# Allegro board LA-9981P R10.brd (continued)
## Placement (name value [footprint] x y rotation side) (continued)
PJP102  -  [JUMP_43X118]  140.05 13.39 270 bottom
PJP103  -  [JUMP_43X118]  117.31 13.51 270 bottom
PJP200  -  [JUMP_43X118]  149.32 27.85 90 top
PJP201  -  [JUMP_43X118]  144.81 27.59 90 bottom
PJP203  -  [JUMP_43X39]  155.03 29.36 270 bottom
PJP300  -  [JUMP_43X118]  143.67 140.45 270 top
PJP400  -  [JUMP_43X79]  108.3 20.35 90 bottom
PJP401  -  [JUMP_43X79]  112.11 31.27 90 bottom
PJP600  -  [JUMP_43X79]  213.98 90.82 0 bottom
PJP601  -  [JUMP_43X79]  215.29 96.76 270 top
PJP1100  -  [JUMP_43X118]  182.78 162.32 270 bottom
PJP1101  -  [JUMP_43X118]  188.12 162.32 270 bottom
PJP1200  -  [JUMP_43X118]  192.27 181.37 0 bottom
PJP1300  -  [JUMP_43X79]  195.74 76.19 270 top
PJP1301  -  [JUMP_43X79]  194.66 58.76 270 bottom
PJPDC  -  [ACES_50299-00501-003_5P]  136.9 178.4 270 bottom
PL1  -  [CHT_C8BBPH853025_2P]  140.43 174 270 bottom
PL2  -  [CHT_C8BBPH853025_2P]  132.93 182.51 180 bottom
PL3  -  [CHENG_SMB3025500YA_2P]  155.86 180.26 90 bottom
PL4  -  [CHT_C8BBPH853025_2P]  132.87 166.13 180 bottom
PL100  -  [VISHAY_IHLP-2525CZ-01_2P]  135.35 25.41 0 bottom
PL101  -  [VISHAY_IHLP-2525CZ-01_2P]  120.17 25.57 180 bottom
PL102  -  [CYNTE_PCMB053T-1R0MS_2P]  127.73 31.78 270 bottom
PL200  -  [TAI-T_VMPI0703AR-1R0M-Z01_2P]  145.4 15.12 0 bottom
PL201  -  [L_1812-1806]  165.32 20.69 270 bottom
PL301  -  [CYNTE_PCMB063T-1R0MS_2P]  144.08 150.59 270 bottom
PL302  -  [L_1812-1806]  134.42 158.32 0 bottom
PL400  -  [TAIYO_NRS4018T1R0NDGJ_2P]  107.58 28.97 90 bottom
PL501  -  [L_1812-1806]  135.09 146.53 90 bottom
PL502  -  [TOKO_FDUE1040J-H-R36M-P3_4P]  109.67 140.16 180 bottom
PL600  -  [TAIYO_NRS4018T1R0NDGJ_2P]  219.55 94.6 90 bottom
PL701  -  [TOKO_FDVE1040-H-2R2M-P3_2P]  155.38 172.6 180 bottom
PL702  -  [CYNTE_PCMB053T-1R0MS_2P]  146.89 163.46 0 bottom
PL800  -  [L_1812-1806]  217.55 77.93 180 top
PL802  -  [MAG_MMD-12CE-R36M-M1L_2P]  211.17 74.49 90 bottom
PL1100  -  [TAI-T_HCB2012KF-121T50_2P]  175.16 177.38 90 top
PL1101  -  [PANAS_ETQP3W2R2WFN_2P]  177.13 170.14 90 bottom
PL1200  -  [CYNTE_PCMB063T-1R0MS_2P]  183.29 181.24 0 bottom
PL1201  -  [L_1812-1806]  171.44 178.76 0 bottom
PL1300  -  [VISHAY_IHLP-2525CZ-01_2P]  195.55 71.38 90 bottom
PQ1  -  [2N7002DW-T-R7_SOT363-6]  128.22 173.52 0 top
PQ2  -  [2N7002DW-T-R7_SOT363-6]  128.9 168.81 270 top
PQ3  -  [2N7002DW-T-R7_SOT363-6]  128.96 163.6 270 top
PQ4  -  [SSM3K7002FU_SC70-3]  128.17 179.34 0 top
PQ5  -  [RHU002N06_SOT323-3]  133.89 187.37 0 bottom
PQ6  -  [FDV301N_NL_SOT23-3]  128.97 186.57 90 bottom
PQ101  -  [SIS412DN-T1-GE3_POWERPAK8-5]  133.1 26.55 90 top
PQ102  -  [SIS412DN-T1-GE3_POWERPAK8-5]  130.23 24.72 270 top
PQ103  -  [SIS412DN-T1-GE3_POWERPAK8-5]  121.78 28.7 270 top
PQ104  -  [SIS412DN-T1-GE3_POWERPAK8-5]  124.65 22.93 90 top
PQ200  -  [SIS412DN-T1-GE3_POWERPAK8-5]  154.68 16.29 90 bottom
PQ201  -  [SIS412DN-T1-GE3_POWERPAK8-5]  157.04 14.46 270 bottom
PQ701  -  [CSD87312Q3E_SON8-4]  140.24 167.98 0 bottom
PQ702  -  [AO4407AL_SO8]  147.12 178.89 90 bottom
PQ703  -  [MDU1516URH_POWERDFN56-8-5]  156.11 169.3 180 top
PQ704  -  [MDU1516URH_POWERDFN56-8-5]  149.77 169.32 180 top
PQ705  -  [MDU1511RH_POWERDFN56-8-5]  159.54 171.17 90 top
PQ706  -  [SSM3K7002FU_SC70-3]  135.79 168.22 180 top
PQ708  -  [SSM3K7002FU_SC70-3]  171.48 173.11 0 top
PQ800  -  [SIR472DP-T1-GE3_POWERPAK8-5]  205.77 69.54 270 top
PQ801  -  [SIR818DP-T1_POWERPAK-SO8-5]  214.09 65.47 270 bottom
PQ802  -  [SIR818DP-T1_POWERPAK-SO8-5]  214.09 71.26 270 bottom
PQ803  -  [SIR472DP-T1-GE3_POWERPAK8-5]  205.77 75.39 270 top
PQ1100  -  [SIS412DN-T1-GE3_POWERPAK8-5]  175.38 172.25 0 top
PQ1101  -  [SIS412DN-T1-GE3_POWERPAK8-5]  180.28 174.79 270 bottom
PQ1201  -  [2N7002W-T-R7_SOT323-3]  173.45 186.99 0 bottom
PR1  -  [R_0402]  128.63 171.02 0 top
PR2  -  [R_0402]  131.94 171.71 0 top
PR3  -  [R_0402]  132.35 185.62 0 top
PR4  -  [R_0402]  130.57 185.62 0 top
PR5  -  [R_1206]  131.27 175.59 270 top
PR6  -  [R_0402]  132.5 182.7 180 top
PR7  -  [R_0402]  128.86 177.49 0 top
PR8  -  [R_0402]  134.22 187.46 180 top
PR9  -  [R_0402]  134.28 182.7 180 top
PR10  -  [R_0402]  129.77 176.6 180 top
PR15  -  [R_0402]  137.63 184.78 90 bottom
PR16  -  [R_0402]  136.76 184.92 180 bottom
PR17  -  [R_0402]  138.52 184.78 90 bottom
PR18  -  [R_0402]  141.88 183.65 0 top
PR20  -  [R_0402]  141.88 184.54 0 top
PR23  -  [R_0402]  129.94 179.91 0 top
PR24  -  [R_0402]  181.96 45.02 90 bottom
PR26  -  [R_0402]  130.85 181.68 180 top
PR27  -  [R_0402]  129.11 178.89 0 top
PR28  -  [R_0402]  128.38 166.38 180 top
PR29  -  [R_0402]  127.65 170 0 top
PR30  -  [R_0402]  127.54 161.8 90 top
PR31  -  [R_0402]  131.98 167.7 90 top
PR32  -  [R_0402]  132.11 162.71 270 top
PR33  -  [R_0402]  130.51 166.32 0 top
PR100  -  [R0402_0OHM]  120.98 13.13 180 top
PR101  -  [R0402_0OHM]  120.98 14.91 180 top
PR102  -  [R_0402]  120.98 14.02 180 top
PR103  -  [R_0402]  132.44 16.68 180 top
PR104  -  [R_0402]  126.71 12.98 270 top
PR105  -  [R_0402]  125.82 12.98 270 top
PR106  -  [R_0402]  125.72 12.99 270 bottom
PR107  -  [R_0402]  130.71 12.06 90 top
PR108  -  [R_0402]  131.6 12.98 270 top
PR109  -  [R_0402]  128.93 12.06 90 top
PR111  -  [R_0402]  124.12 17.28 180 top
PR112  -  [R_1206]  119.98 25.06 270 top
PR113  -  [R_1206]  134.97 24.87 270 top
PR114  -  [R_0402]  124.12 15.5 180 top
PR200  -  [R_0603]  154.85 22.95 90 bottom
PR201  -  [R0402_0OHM]  162.92 25.22 180 bottom
PR202  -  [R0402_0OHM]  162.92 27 180 bottom
PR203  -  [R_1206]  161.32 10.74 0 bottom
PR204  -  [R_0402]  161.47 29.11 180 bottom
PR205  -  [R_0402]  158.59 20.28 90 bottom
PR206  -  [R_0603]  162.09 21.42 270 bottom
PR207  -  [R_0402]  161.47 28.22 180 bottom
PR208  -  [R_0402]  162.92 23.44 180 bottom
PR300  -  [R0402_0OHM]  148.17 148.34 0 bottom
PR301  -  [R_0402]  148.17 149.23 0 bottom
PR302  -  [R_1206]  139.54 146.56 90 bottom
PR303  -  [R0603_0OHM]  147.04 156.85 0 bottom
PR304  -  [R_0402]  149.08 152.78 180 bottom
PR305  -  [R_0402]  148.62 153.72 90 bottom
PR306  -  [R_0402]  148.17 151.89 0 bottom
PR307  -  [R_0402]  149.39 155.5 90 bottom
PR308  -  [R_0402]  149.08 151.01 180 bottom
PR401  -  [R0402_0OHM]  113.68 26.85 270 bottom
PR402  -  [R_0402]  111.9 23.78 90 bottom
PR403  -  [R_0402]  112.79 24.69 270 bottom
PR404  -  [R_0402]  112.79 26.85 270 bottom
PR405  -  [R_0603]  108.34 26.97 180 bottom
PR501  -  [R_0402]  88.61 141.22 90 bottom
PR502  -  [R_0402]  85.94 141.22 90 bottom
PR503  -  [R_0402]  88.48 138.94 90 top
PR504  -  [R_0402]  86.83 141.22 90 bottom
PR505  -  [R_0402]  86.71 138.94 90 top
PR506  -  [R_0402]  85.82 138.94 90 top
PR507  -  [R_0402]  87.72 141.22 90 bottom
PR508  -  [R_0402]  91.66 142.19 270 bottom
PR509  -  [R_0402]  87.6 138.94 90 top
PR510  -  [R_0402]  87.01 137.23 0 top
PR512  -  [R_0402]  89.37 138.94 90 top
PR513  -  [R_0402]  91.15 138.94 90 top
PR514  -  [R_0402]  90.77 141.29 90 bottom
PR515  -  [R_0402]  92.98 141.74 0 bottom
PR516  -  [R_0603]  83.98 135.77 0 bottom
PR517  -  [R_0402]  92.98 140.85 0 bottom
PR518  -  [R_0402]  92.93 143.06 90 bottom
PR519  -  [R_0603]  88.87 131.89 90 bottom
PR522  -  [R0402_0OHM]  85.46 139.01 180 bottom
PR524  -  [R_0402]  84.55 137.23 0 bottom
PR526  -  [R_0402]  87.79 132.59 90 bottom
PR528  -  [R_0402]  86.9 132.59 90 bottom
PR529  -  [R_0402]  92.66 132.6 0 bottom
PR530  -  [R_0402]  84.53 134.69 0 bottom
PR531  -  [R_0402]  90.9 132.66 90 bottom
PR532  -  [R_0402]  93.58 133.49 180 bottom
PR533  -  [R_0402]  85.45 134.69 180 top
PR534  -  [R_1206]  108.42 143.2 0 top
PR535  -  [R0402_0OHM]  85.46 138.12 180 bottom
PR536  -  [R_0603]  116.77 140.05 0 bottom
PR540  -  [R_0402]  84.53 135.58 0 top
PR601  -  [R0402_0OHM]  218.29 93.36 180 top
PR602  -  [R_0402]  221.26 89.79 90 bottom
PR603  -  [R_0402]  222.16 88.91 180 bottom
PR604  -  [R_0402]  219.17 93.37 270 top
PR605  -  [R_0603]  216.06 95.13 270 bottom
PR701  -  [R_0402]  142.9 163.89 90 bottom
PR702  -  [R_1206_4P-D]  139.7 162.19 0 bottom
PR703  -  [R_0402]  143.79 164.81 270 bottom
PR704  -  [R0402_0OHM]  166.78 165.95 270 bottom
PR705  -  [R_1206]  164.49 163.08 90 top
PR706  -  [R_0402]  147.36 183.91 180 bottom
PR707  -  [R_0402]  169.07 164.97 90 top
PR708  -  [R0402_0OHM]  167.67 173.04 90 top
PR709  -  [R_0603]  163.92 169.56 180 top
PR710  -  [R0402_0OHM]  168.56 173.04 90 top
PR711  -  [R_0402]  172.25 167.21 180 top
PR712  -  [R_0402]  170.02 165.89 270 top
PR713  -  [R_0402]  171.34 171.65 0 top
PR714  -  [R0402_0OHM]  172.25 170.76 180 top
PR715  -  [R0402_0OHM]  172.25 169.87 180 top
PR716  -  [R_1206_4P-D]  143.73 176.64 90 bottom
PR717  -  [R0402_0OHM]  167.67 165.95 270 bottom
PR720  -  [R_1206]  138.2 169.94 180 top
PR721  -  [R_0402]  143.81 165.68 180 bottom
PR722  -  [R_1206]  156.37 177.01 0 top
PR723  -  [R_0402]  171.34 166.32 0 top
PR724  -  [R_0402]  171.07 176.22 0 top
PR802  -  [R0603_0OHM]  201.39 60.08 90 bottom
PR803  -  [R0402_0OHM]  209.91 56.02 180 bottom
PR804  -  [R0402_0OHM]  206.71 57.1 0 top
PR805  -  [R_1206]  211.17 62.69 0 top
PR806  -  [R0402_0OHM]  209.91 56.91 180 bottom
PR807  -  [R0402_0OHM]  209.91 58.68 180 bottom
PR808  -  [R_0402]  209.91 54.24 180 bottom
PR809  -  [R0402_0OHM]  209.91 57.8 180 bottom
PR810  -  [R0402_0OHM]  208.7 59 180 top
PR811  -  [R0402_0OHM]  206.96 60.46 0 top
PR812  -  [R0402_0OHM]  209.91 59.57 180 bottom
PR813  -  [R_0402]  203.37 51.95 180 bottom
PR814  -  [R0603_0OHM]  205.9 61.73 90 bottom
PR815  -  [R_0402]  206.72 54.35 90 top
PR816  -  [R_0402]  199.11 56.59 180 bottom
PR817  -  [R_0402]  206.04 52.84 180 bottom
PR818  -  [R_0402]  203.37 51.06 180 bottom
PR819  -  [R_0402]  207.79 58.11 0 top
PR820  -  [R_0402]  205.32 53.49 270 top
PR821  -  [R_0402]  204.24 53.74 270 bottom
PR822  -  [R_0603]  201.51 58.68 180 bottom
PR823  -  [R0603_0OHM]  201.51 58.68 180 top
PR824  -  [R_0402]  201.58 60.67 270 top
PR825  -  [R_0402]  201.59 55.51 180 bottom
PR826  -  [R_0402]  213.91 59.51 180 bottom
PR827  -  [R_0402]  199.11 57.48 180 bottom
PR828  -  [R_0402]  209.64 58.1 90 top
PR829  -  [R_0402]  199.1 61.05 270 bottom
PR830  -  [R0402_0OHM]  198.21 61.05 270 bottom
PR833  -  [R_0402]  200.69 56.41 270 top
PR834  -  [R_0402]  211.22 59.57 0 bottom
PR835  -  [R_0402]  213.91 57.99 180 bottom
PR836  -  [R_0402]  211.22 57.99 0 bottom
PR837  -  [R_0402]  213.91 57.1 180 bottom
PR838  -  [R_0402]  211.22 57.1 0 bottom
PR839  -  [R_0402]  213.91 55.57 180 bottom
PR840  -  [R_0402]  211.22 55.57 0 bottom
PR842  -  [R_0402]  208.99 55.13 0 bottom
PR845  -  [R0402_0OHM]  200.63 54.63 270 bottom
PR846  -  [R0402_0OHM]  203.37 53.73 180 bottom
PR1101  -  [R_0603]  185.07 169.17 180 top
PR1102  -  [R_0402]  187.28 171.14 0 bottom
PR1103  -  [R0402_0OHM]  189.89 173.19 270 top
PR1104  -  [R_1206]  177.57 170.44 0 top
PR1105  -  [R_0402]  188.19 173.81 180 bottom
PR1107  -  [R_0402]  189.89 172.87 270 bottom
PR1108  -  [R_0402]  188.19 172.92 180 bottom
PR1110  -  [R_0402]  189.21 169.68 180 top
PR1200  -  [R0603_0OHM]  177.01 185.12 90 bottom
PR1201  -  [R_0402]  184.88 186.18 90 bottom
PR1202  -  [R_0402]  182.21 186.18 90 bottom
PR1203  -  [R_0402]  181.32 187.09 270 bottom
PR1204  -  [R_0402]  178.36 187.47 180 bottom
PR1206  -  [R0402_0OHM]  185.77 186.18 90 bottom
PR1207  -  [R_1206]  185.13 176.67 180 bottom
PR1208  -  [R_0402]  180.45 188.22 180 bottom
PR1209  -  [R_0402]  179.54 185.54 90 bottom
PR1210  -  [R0402_0OHM]  179.53 187.34 0 bottom
PR1211  -  [R_0402]  176.06 187.46 180 bottom
PR1212  -  [R_0402]  172.55 183.27 0 bottom
PR1213  -  [R_0402]  170.72 184.17 270 bottom
PR1214  -  [R_0402]  171.61 183.26 90 bottom
PR1300  -  [R_0402]  197.84 65.99 180 bottom
PR1301  -  [R_0402]  195.99 62.61 90 top
PR1302  -  [R_0402]  196.88 63.52 270 top
PR1303  -  [R_1206]  196.62 68.91 270 top
PR1304  -  [R_0402]  197.89 65.11 270 bottom
PU100  -  [TPS51225CRUKR_QFN20_3X3]  127.03 14.52 0 top
PU200  -  [RT8207MZQW_WQFN20_3X3]  157.71 26.38 0 bottom
PU300  -  [SY8206DQNC_QFN10_3X3]  145.59 153.63 90 bottom
PU400  -  [SY8003DFC_DFN8_2X2]  110.87 24.22 180 bottom
PU501  -  [TPS51622RSM_QFN32_4X4]  87.18 136.02 90 bottom
PU502  -  [CSD97374CQ4M_SON8_3P5X4P5-S]  111.9 139.63 90 bottom
PU600  -  [SY8003DFC_DFN8_2X2]  220.04 90.16 180 bottom
PU701  -  [BQ24738RGRR_QFN20_3P5X3P5]  166.99 167.7 0 top
PU800  -  [ISL62881HRZ-T_QFN28_4X4]  206.59 55.46 180 bottom
PU1100  -  [TPS51212DSCR_SON10_3X3]  188.26 171.29 90 top
PU1200  -  [SY8206DQNC_QFN10_3X3]  180.29 183.54 180 bottom
PU1300  -  [SY8036DBC_DFN10_3X3]  193.66 65.57 0 bottom
Q8  -  [2N7002K_SOT23-3]  87.21 23.02 180 top
Q2307  -  [2N7002K_SOT23-3]  182.97 60.17 180 top
Q2308  -  [2N7002K_SOT23-3]  147.9 121.17 270 top
QA5  -  [DMN66D0LDW-7_SOT363-6]  25.85 27.08 270 bottom
QA6  -  [DMN66D0LDW-7_SOT363-6]  15.93 20.7 90 bottom
QC1  -  [DMN66D0LDW-7_SOT363-6]  144.74 110.07 0 bottom
QC3  -  [2N7002K_SOT23-3]  134.62 130.95 180 bottom
QD2  -  [BSS138-G_SOT23-3]  48.7 64.91 90 top
QD18  -  [2N7002K_SOT23-3]  57.9 16.58 90 top
QD19  -  [2N7002K_SOT23-3]  61.48 16.6 270 top
QD20  -  [2N7002K_SOT23-3]  70.62 15.07 0 top
QH1  -  [DMN66D0LDW-7_SOT363-6]  148.21 115.18 270 bottom
QM30  -  [2N7002K_SOT23-3]  102.42 147.33 90 top
QS2  -  [SI3456BDV-T1-E3_TSOP6]  220.85 121.09 0 bottom
QS3  -  [2N7002KW_SOT323-3]  221.49 125.83 0 bottom
QV14  -  [DMN66D0LDW-7_SOT363-6]  188.48 101.22 0 bottom
QV15  -  [DMN66D0LDW-7_SOT363-6]  178.54 93.83 180 top
QV22  -  [AP2301GN-HF_SOT23-3]  184.15 93.73 90 bottom
QV24  -  [2N7002K_SOT23-3]  179 90.24 270 bottom
QV25  -  [2N7002K_SOT23-3]  174.36 90.05 270 bottom
QV28  -  [2N7002K_SOT23-3]  183.16 90.53 0 top
QX1  -  [2N7002KW_SOT323-3]  216.84 176.48 90 top
QX2  -  [SI3457CDV-T1-GE3_TSOP6]  223.09 176.67 180 top
QX3  -  [2N7002K_SOT23-3]  19.12 106.82 90 bottom
QX4  -  [DMN66D0LDW-7_SOT363-6]  15.19 106.76 0 top
QX5  -  [MMBT3904_NL_SOT23-3]  16.6 113.14 180 bottom
QX6  -  [DMN66D0LDW-7_SOT363-6]  196.11 163.13 90 top
R1  -  [R_0402]  93.64 134.06 180 top
R2  -  [R_0402]  91.86 134.06 180 top
R10  -  [R_0402]  85.69 24.72 270 top
R16  -  [R_0402]  87.84 19.19 0 top
R159  -  [R_0402]  147.53 102.56 0 top
R245  -  [R_0603]  93.12 129.93 90 bottom
R248  -  [R0402_0OHM]  80.85 117.8 0 bottom
R250  -  [R_0402]  91.98 122.11 90 top
R251  -  [R0402_0OHM]  90.52 129.69 270 bottom
R252  -  [R_0402]  80.85 118.69 0 bottom
R253  -  [R_0402]  81.77 120.6 180 bottom
R254  -  [R_0402]  84.12 118.69 180 bottom
R255  -  [R_0402]  83.2 120.98 0 bottom
R256  -  [R_0402]  79.92 119.58 0 bottom
R257  -  [R0402_0OHM]  79.92 120.53 180 bottom
R264  -  [R0603_0OHM]  150.97 104.66 180 top
R265  -  [R0402_0OHM]  118.33 98.19 270 top
R267  -  [R0805_0OHM]  123.83 140.85 0 bottom
R286  -  [R_0402]  92.04 129.69 270 bottom
R416  -  [R0402_0OHM]  143.04 19.76 180 bottom
R2313  -  [R_0402]  96.8 25.59 90 top
R2314  -  [R_0603]  184.62 62.49 270 top
R2315  -  [R_0603]  146.9 124.09 270 top
R2318  -  [R_0402]  93.44 25.65 90 top
R2329  -  [R_0402]  140.87 109.06 0 bottom
R2330  -  [R_0402]  135.28 103.66 270 bottom
R2331  -  [R_0402]  147.04 109 270 bottom
R2332  -  [R_0402]  147.93 110.06 180 bottom
R2333  -  [R_0402]  142.55 115.86 180 bottom
R2334  -  [R_0402]  142.55 116.75 180 bottom
R2335  -  [R_0402]  142.55 117.63 180 bottom
R2336  -  [R_0402]  125.72 96.24 90 top
R2337  -  [R_0402]  134.01 99.65 270 bottom
R2338  -  [R_0402]  133.12 99.65 270 bottom
R2341  -  [R_0402]  75.29 114.06 180 top
R2346  -  [R_0402]  79.91 122.5 90 bottom
R2347  -  [R_0402]  43.97 63.82 90 top
R2348  -  [R_0402]  43.08 62.98 270 top
R2349  -  [R_0402]  43.97 62.98 270 top
R2350  -  [R_0402]  42.19 62.98 270 top
R2351  -  [R_0402]  44.86 63.82 90 top
R2352  -  [R_0402]  41.3 62.98 270 top
R2354  -  [R_0402]  187.42 32.7 90 top
R2355  -  [R_0402]  32.15 20.52 0 top
R2356  -  [R_0402]  127.24 97.04 90 bottom
R2357  -  [R_0402]  130.9 97.48 180 bottom
R2358  -  [R_0402]  129.05 97.04 90 bottom
R2359  -  [R_0402]  128.16 97.04 90 bottom
RA1  -  [R_0402]  30.57 28.28 270 top
RA2  -  [R_0402]  21.84 26.56 0 bottom
RA3  -  [R_0402]  28.73 23.56 90 bottom
RA4  -  [R0402_0OHM]  30.57 25.59 90 top
RA5  -  [R_0402]  17.62 25.49 270 bottom
RA6  -  [R_0402]  15.78 25.49 270 bottom
RA7  -  [R_0402]  16.69 25.49 270 bottom
RA8  -  [R_0402]  25.66 14.74 90 top
RA9  -  [R_0402]  24.78 14.74 90 top
RA19  -  [R_0402]  36.62 23.63 180 top
RA29  -  [R0603_0OHM]  23.9 21.6 0 bottom
RA30  -  [R0603_0OHM]  26.57 23.76 270 bottom
RA31  -  [R0603_0OHM]  23.27 26.81 90 top
RA32  -  [R0603_0OHM]  26.84 12.05 0 top
RA51  -  [R_0402]  29.68 25.59 90 top
RA53  -  [R_0402]  15.84 23.37 90 top
RA55  -  [R_0402]  24.04 11.61 0 bottom
RA56  -  [R_0402]  24.04 12.49 0 bottom
RA79  -  [R_0402]  33.93 24.52 0 top
RA80  -  [R_0402]  21.82 20.14 180 bottom
RA81  -  [R_0402]  34.84 25.41 180 top
RA82  -  [R_0402]  21.82 21.03 180 bottom
RA83  -  [R_0402]  20.04 20.14 180 top
RA84  -  [R_0402]  20.04 21.92 180 top
RA130  -  [R_0402]  33.06 21.47 180 top
RA153  -  [R_0402]  28.48 26.82 270 top
RA165  -  [R_0402]  21.82 20.14 180 top
RA166  -  [R_0402]  21.82 21.03 180 top
RA1109  -  [R_0402]  16.73 23.37 90 top
RC1  -  [R_0402]  132.3 97.31 270 bottom
RC2  -  [R_0402]  133.19 96.54 270 bottom
RC3  -  [R_0402]  125.45 97.04 90 bottom
RC4  -  [R_0402]  146 98.25 0 bottom
RC5  -  [R_0402]  131.28 94.74 90 top
RC6  -  [R_0402]  132.17 94.74 90 top
RC7  -  [R_0402]  134.9 98.74 90 bottom
RC8  -  [R_0402]  126.34 97.04 90 bottom
RC9  -  [R_0402]  135.08 115.71 0 top
RC10  -  [R_0402]  204.05 9.8 270 bottom
RC11  -  [R_0402]  131.61 118.31 180 top
RC12  -  [R_0402]  116.23 134.46 0 top
RC13  -  [R_0402]  115.54 129.22 90 bottom
RC14  -  [R_0402]  97.96 91.07 90 bottom
RC15  -  [R_0402]  94.59 91.07 90 bottom
RC16  -  [R_0402]  96.99 90.44 180 bottom
RC17  -  [R_0402]  97.07 93.74 90 bottom
RC18  -  [R_0402]  94.4 93.74 90 bottom
RC19  -  [R_0402]  96.18 93.74 90 bottom
RC20  -  [R_0402]  97.05 92.86 0 bottom
RC21  -  [R_0402]  94.41 92.86 180 bottom
RC22  -  [R_0402]  96.19 92.86 180 bottom
RC23  -  [R_0402]  97.96 94.65 270 bottom
RC24  -  [R_0402]  93.51 94.65 270 bottom
RC25  -  [R_0402]  95.29 94.65 270 bottom
RC26  -  [R0402_0OHM]  61.63 106.21 270 top
RC27  -  [R_0402]  136.82 96.39 180 top
RC28  -  [R_0402]  148.42 108.98 0 bottom
RC29  -  [R_0402]  148.11 111.72 0 bottom
RC31  -  [R_0402]  147.87 108.79 180 top
RC32  -  [R_0402]  144.38 114.44 180 bottom
RC33  -  [R0402_0OHM]  126.98 98.18 180 top
RC34  -  [R_0402]  130.9 110.26 270 top
RC35  -  [R_0402]  134.08 97.31 270 top
RC36  -  [R_0402]  129.77 114.35 180 top
RC37  -  [R_0402]  133.44 109.17 180 bottom
RC41  -  [R0402_0OHM]  128 97.05 180 top
RC42  -  [R0402_0OHM]  134.97 96.39 90 top
RC43  -  [R0402_0OHM]  74.49 106.46 180 bottom
RC44  -  [R0402_0OHM]  74.54 104.21 180 bottom
RC45  -  [R0402_0OHM]  74.54 105.12 180 bottom
RC46  -  [R0402_0OHM]  65.94 104.36 0 bottom
RC48  -  [R_0402]  65.44 90.12 90 bottom
RC49  -  [R_0402]  63.67 90.12 90 bottom
RC50  -  [R_0402]  62.78 90.12 90 bottom
RC51  -  [R_0402]  62.78 102.27 270 bottom
RC52  -  [R_0402]  61.89 90.12 90 bottom
RC56  -  [R_0402]  58.71 101.36 90 bottom
RC57  -  [R0402_0OHM]  75.29 114.95 180 top
RC58  -  [R_0402]  89.17 119.58 0 top
RC59  -  [R0402_0OHM]  84.62 110.69 180 bottom
RC60  -  [R_0402]  88.3 120.03 90 top
RC62  -  [R_0402]  83.71 111.58 0 bottom
RC63  -  [R_0402]  89.77 112.02 180 top
RC64  -  [R_0402]  62.78 88.68 270 bottom
RC65  -  [R_0402]  83.71 109.8 0 bottom
RC66  -  [R_0402]  87.73 128.22 90 bottom
RC67  -  [R_0402]  89.56 120.93 0 top
RC68  -  [R_0402]  89.32 98.15 270 top
RC69  -  [R_0402]  90.21 98.15 270 top
RC70  -  [R_0402]  88.43 98.15 270 top
RC71  -  [R_0402]  117.75 124.03 0 top
RC72  -  [R_0402]  103.34 128.73 90 bottom
RC73  -  [R_0402]  137.13 118.45 270 bottom
RC74  -  [R_0402]  125.19 116.2 90 top
RC75  -  [R_0402]  131.04 134.81 180 bottom
RC76  -  [R_0402]  136.25 119.33 180 bottom
RC77  -  [R_0402]  129.45 118.57 180 top
RC78  -  [R_0402]  135.17 129.21 180 bottom
RC81  -  [R0402_0OHM]  129.25 133.92 90 bottom
RC84  -  [R_0402]  131.04 133.92 180 bottom
RC87  -  [R_0402]  126.27 123.7 90 top
RC88  -  [R_0402]  133.49 119.2 0 bottom
RC89  -  [R_0402]  133.14 129.21 90 bottom
RC90  -  [R_0402]  122.51 110.41 90 top
RC91  -  [R_0402]  113.74 129.3 0 bottom
RC97  -  [R_0402]  130.89 108.47 0 top
RC98  -  [R_0402]  128.54 119.45 0 top
RC99  -  [R_0402]  134.2 115.89 90 top
RC100  -  [R_0402]  136 116.6 180 top
RC101  -  [R_0402]  124.28 97.15 270 bottom
RC102  -  [R_0402]  143.85 119.66 0 bottom
RC103  -  [R_0402]  148.19 112.6 180 bottom
RC104  -  [R_0402]  141.78 109.94 180 bottom
RC105  -  [R_0402]  132.26 130.12 270 bottom
RC106  -  [R_0402]  136.25 121.99 180 bottom
RC107  -  [R_0402]  145 111.06 0 bottom
RC108  -  [R_0402]  136.64 121.12 180 bottom
RC110  -  [R_0402]  145 111.92 0 bottom
RC111  -  [R_0402]  136.63 120.22 180 bottom
RC112  -  [R_0402]  134.6 119.33 180 top
RC113  -  [R_0402]  133.68 118.44 0 top
RC116  -  [R_0402]  133.49 118.31 0 bottom
RC118  -  [R_0402]  136.25 125.87 180 bottom
RC119  -  [R_0402]  136.25 118.44 180 bottom
RC120  -  [R_0402]  146.11 112.8 180 bottom
RC121  -  [R_0402]  136.5 114.25 180 bottom
RC122  -  [R_0402]  134.41 125.58 180 bottom
RC123  -  [R_0402]  133.49 120.09 0 bottom
RC124  -  [R_0402]  148.43 107.21 0 bottom
RC125  -  [R_0402]  148.43 108.1 0 bottom
RC126  -  [R0603_0OHM]  123.35 130.63 90 bottom
RC127  -  [R_0402]  123.21 98.19 180 top
RC128  -  [R_0402]  123.21 97.31 180 top
RC129  -  [R_0402]  123.21 96.43 180 top
RC130  -  [R_0402]  85.56 110.68 90 bottom
RC131  -  [R_0402]  124.43 130.62 90 bottom
RC132  -  [R_0402]  91.72 115.66 0 top
RC133  -  [R_0402]  122.27 131.47 270 bottom
RC134  -  [R_0402]  123.39 97.15 270 bottom
RC135  -  [R_0402]  84.62 108.91 180 bottom
RC138  -  [R_0402]  82.6 113.5 180 bottom
RC139  -  [R_0402]  108.36 129.69 270 bottom
RC140  -  [R_0402]  109.31 129.69 270 bottom
RC141  -  [R0402_0OHM]  84.12 120.03 180 bottom
RC163  -  [R_0402]  89.58 124.03 180 top
RC362  -  [R_0402]  60.99 102.26 270 bottom
RD1  -  [R0402_0OHM]  43.54 70.05 180 top
RD3  -  [R_0402]  49.48 63.45 0 top
RD4  -  [R0402_0OHM]  83.46 63.45 0 top
RD5  -  [R0402_0OHM]  83.46 62.56 0 top
RD6  -  [R_0402]  102.44 68.78 0 top
RD7  -  [R_0402]  102.44 67.89 0 top
RD8  -  [R0402_0OHM]  121.33 70.75 180 top
RD10  -  [R0402_0OHM]  162.07 62.56 0 top
RD12  -  [R_0402]  182.79 65.73 180 top
RD13  -  [R_0402]  182.78 70.48 90 top
RD14  -  [R_0402]  34.65 10.81 180 top
RD15  -  [R_0402]  43.98 10.74 180 top
RD16  -  [R_0402]  49.9 13.86 270 top
RD17  -  [R_0402]  49.01 13.86 270 top
RD18  -  [R_0402]  57.93 12.9 0 top
RD45  -  [R_0402]  54 15.9 270 top
RD46  -  [R_0402]  58.82 13.9 180 top
RD47  -  [R_0402]  65.32 16.33 90 top
RD48  -  [R_0402]  49.63 18.48 0 top
RD49  -  [R_0402]  50.62 15 0 top
RD50  -  [R_0402]  73.17 17.17 270 top
RD51  -  [R_0402]  54 14.11 270 top
RD52  -  [R_0402]  53.14 14.11 270 top
RE1  -  [R_0402]  93.77 121.8 180 top
RE2  -  [R_0402]  128.11 94.8 90 top
RE3  -  [R_0402]  197.2 53.78 90 top
RE5  -  [R_0402]  195.42 54.7 270 top
RE7  -  [R_0402]  192.12 55.8 270 top
RE8  -  [R_0402]  199.47 38.94 0 top
RE9  -  [R_0402]  187.04 54.19 270 top
RE10  -  [R_0402]  186.15 54.19 270 top
RE11  -  [R_0402]  181.35 34.16 270 top
RE12  -  [R_0402]  179.59 40.41 180 top
RE18  -  [R_0402]  195.93 33.81 270 top
RE36  -  [R_0402]  178.58 45.86 0 top
RE37  -  [R0402_0OHM]  127.84 98.18 0 top
RE43  -  [R_0402]  179.43 41.68 180 top
RE44  -  [R0402_0OHM]  180.5 54.38 270 top
RE47  -  [R_0402]  178.27 50.35 90 top
RE49  -  [R_0402]  194.54 27.57 180 top
RE50  -  [R_0402]  50.97 105.23 180 bottom
RE60  -  [R_0402]  228.31 156.4 90 bottom
RE71  -  [R_0402]  178.51 42.57 0 top
RE326  -  [R_0402]  179.49 48.91 180 top
RG1  -  [R_0402]  74.96 45.74 270 top
RG2  -  [R_0402]  68.66 45.62 270 top
RG3  -  [R_0402]  146.87 103.22 270 bottom
RG4  -  [R_0402]  70.95 44.7 90 top
RG5  -  [R_0402]  72.93 39.01 270 top
RG6  -  [R_0402]  119.24 136.55 90 top
RG7  -  [R_0402]  174.17 98.21 90 bottom
RG8  -  [R_0402]  35.2 75.64 90 bottom
RL19  -  [R_0603]  20.29 85.55 270 top
RL20  -  [R_0603]  20.29 81.74 90 top
RL27  -  [R_0402]  42.88 79.39 0 bottom
RL31  -  [R_0402]  35.08 79.37 90 bottom
RL33  -  [R_0402]  42.97 85.55 180 bottom
RL34  -  [R_0402]  42.97 83.77 180 bottom
RL35  -  [R_0402]  42.97 84.66 180 bottom
RL37  -  [R_0402]  37.05 88.2 90 bottom
RL38  -  [R_0402]  41.43 79.75 90 bottom
RM11  -  [R_0402]  115.09 147.7 90 top
RM13  -  [R_0402]  115.98 148.61 270 top
RM25  -  [R0805_0OHM]  120.68 148.22 180 top
RM26  -  [R0805_0OHM]  96 148.47 180 top
RM110  -  [R_0402]  104.17 148.68 270 top
RP36  -  [RP_0804_8P4R]  189.4 54.24 90 top
RP37  -  [RP_0804_8P4R]  138.97 115.16 0 bottom
RP39  -  [RP_0804_8P4R]  140.12 119.46 180 bottom
RP40  -  [RP_0804_8P4R]  138.46 112.04 0 bottom
RP41  -  [RP_0804_8P4R]  142.34 111.29 0 bottom
RP42  -  [RP_0804_8P4R]  148.18 112.74 180 top
RP43  -  [RP_0804_8P4R]  143.11 122.32 180 bottom
RP44  -  [RP_0804_8P4R]  86.46 123.7 180 bottom
RP45  -  [RP_0804_8P4R]  74.94 111.4 180 top
RP46  -  [RP_0804_8P4R]  60.6 89.48 90 bottom
RP47  -  [RP_0804_8P4R]  175.62 105.86 90 top
RP48  -  [RP_0804_8P4R]  86.89 110.99 0 bottom
RP49  -  [RP_0804_8P4R]  138.46 109.24 0 bottom
RP50  -  [RP_0804_8P4R]  132.18 111.34 180 top
RP51  -  [RP_0804_8P4R]  130.95 130.05 90 bottom
RP52  -  [RP_0804_8P4R]  20.02 109.73 90 bottom
RP53  -  [RP_0804_8P4R]  135.72 123.28 0 bottom
RP54  -  [RP_0804_8P4R]  132.18 114.13 180 top
RP55  -  [RP_0804_8P4R]  139.59 97.45 270 top
RP56  -  [RP_0804_8P4R]  200.06 175.47 180 top
RP57  -  [RP_0804_8P4R]  196.82 165.69 180 top
RP58  -  [RP_0804_8P4R]  15.21 96.48 180 top
RP59  -  [RP_0804_8P4R]  16.61 101.94 180 top
RP60  -  [RP_0804_8P4R]  184 105.92 90 top
RR1  -  [R_0402]  175 18.07 270 top
RR2  -  [R_0402]  178.21 27.11 90 top
RR3  -  [R_0402]  180.88 20.94 0 top
RS6  -  [R_0402]  222.67 126.3 0 bottom
RS7  -  [R_0402]  215.88 57.86 0 top
RS8  -  [R_0402]  215.88 58.76 0 top
RV54  -  [R0603_0OHM]  32.73 12.77 180 top
RV59  -  [R0603_0OHM]  19.65 25.79 270 top
RV64  -  [R_0402]  178.32 105.99 0 top
RV66  -  [R_0402]  161.72 112.54 180 bottom
RV73  -  [R_0402]  190.86 102.24 180 bottom
RV74  -  [R_0402]  189.97 98.37 180 bottom
RV75  -  [R_0402]  181.7 96.64 90 bottom
RV76  -  [R_0402]  182.59 96.64 90 bottom
RV81  -  [R_0402]  183.48 96.64 90 bottom
RV82  -  [R_0402]  184.37 96.64 90 bottom
RV83  -  [R_0402]  185.26 96.64 90 bottom
RV84  -  [R_0402]  158.51 112.53 0 bottom
RV85  -  [R_0402]  187.29 105.92 90 top
RV89  -  [R_0402]  181.64 104.41 270 top
RV90  -  [R_0402]  179.92 93.4 90 top
RV91  -  [R_0402]  175.16 92.54 270 top
RV93  -  [R_0402]  185.01 100.46 180 bottom
RV95  -  [R_0402]  185.01 101.35 180 bottom
RV97  -  [R_0402]  171.43 102.05 180 bottom
RV103  -  [R_0805]  168.3 127.86 270 top
RV105  -  [R_0402]  175.54 158.49 90 bottom
RV107  -  [R_0402]  189.26 92.13 90 bottom
RV108  -  [R_0402]  189.26 93.91 90 bottom
RV109  -  [R_0402]  173.31 92.59 0 bottom
RV118  -  [R0402_0OHM]  160.56 104.42 270 top
RV119  -  [R0402_0OHM]  182.54 99.13 180 bottom
RV120  -  [R0402_0OHM]  157.45 105.98 90 top
RV121  -  [R0402_0OHM]  186.86 99.2 180 bottom
RV122  -  [R_0402]  183.22 102.25 270 bottom
RV123  -  [R_0402]  173.11 104.27 0 top
RV124  -  [R0402_0OHM]  156.56 103.5 90 top
RV125  -  [R_0402]  178.07 110.56 0 top
RV126  -  [R0402_0OHM]  157.57 100.33 90 top
RV127  -  [R_0402]  161.84 107.83 180 bottom
RV133  -  [R_0402]  169.69 115.83 0 top
RV136  -  [R_0402]  193.43 93.35 0 top
RV137  -  [R_0402]  192.44 91.51 180 top
RV138  -  [R_0402]  210.91 99.05 90 top
RV139  -  [R_0402]  162.03 130.63 180 bottom
RV140  -  [R_0402]  162.02 131.52 180 bottom
RV141  -  [R_0402]  196.14 101.49 90 bottom
RV142  -  [R_0402]  197.96 105.04 90 bottom
RV143  -  [R_0402]  209.96 99.97 270 top
RV144  -  [R_0402]  207.61 99.37 90 top
RV145  -  [R_0402]  206.66 99.37 90 top
RV146  -  [R_0402]  161.11 129.74 0 bottom
RV147  -  [R_0402]  161.11 132.41 0 bottom
RV148  -  [R_0402]  197.09 103.27 90 bottom
RV149  -  [R_0402]  197.07 105.95 270 bottom
RV150  -  [R_0402]  171.21 154.25 90 top
RV151  -  [R_0402]  170.38 141.08 270 bottom
RV152  -  [R_0402]  187.4 141.13 270 top
RV153  -  [R_0402]  188.1 154.37 90 bottom
RV154  -  [R_0402]  169.43 154.25 90 top
RV155  -  [R_0402]  170.32 154.25 90 top
RV156  -  [R_0402]  170.38 140.21 90 top
RV157  -  [R_0402]  172.16 155.16 270 bottom
RV158  -  [R_0402]  173.95 141.11 180 bottom
RV159  -  [R_0402]  166.26 155.16 270 bottom
RV160  -  [R_0402]  184.73 140.21 90 top
RV161  -  [R_0402]  191.72 155.29 270 top
RV162  -  [R_0402]  185.24 155.22 270 bottom
RV163  -  [R_0402]  187.4 140.21 90 bottom
RV164  -  [R_0402]  188.1 154.37 90 top
RV165  -  [R_0402]  189.05 154.37 90 top
RV166  -  [R_0402]  169.49 141.13 270 top
RV167  -  [R_0402]  171.21 154.25 90 bottom
RV168  -  [R_0402]  172.16 141.13 270 bottom
RV169  -  [R_0402]  167.15 154.25 90 bottom
RV170  -  [R_0402]  185.62 141.08 270 top
RV171  -  [R_0402]  190.83 154.37 90 top
RV172  -  [R_0402]  187.15 154.37 90 bottom
RV173  -  [R_0402]  188.35 141.13 270 bottom
RV174  -  [R_0402]  216.28 131.97 0 top
RV175  -  [R_0402]  216.28 132.86 0 top
RV176  -  [R_0402]  216.28 131.08 0 top
RV177  -  [R_0402]  203.16 132.86 180 bottom
RV178  -  [R_0402]  216.41 115.78 0 bottom
RV179  -  [R_0402]  203.1 115.02 180 top
RV180  -  [R_0402]  216.35 114.89 0 top
RV181  -  [R_0402]  216.35 113.94 0 top
RV182  -  [R_0402]  202.25 131.97 0 top
RV183  -  [R_0402]  217.2 128.36 180 top
RV184  -  [R_0402]  203.16 131.97 180 bottom
RV185  -  [R_0402]  217.2 133.77 180 bottom
RV186  -  [R_0402]  217.32 118.44 180 bottom
RV187  -  [R_0402]  202.18 115.02 0 bottom
RV188  -  [R_0402]  202.18 117.68 0 top
RV189  -  [R_0402]  217.2 111.27 180 top
RV190  -  [R_0402]  203.16 132.86 180 top
RV191  -  [R_0402]  216.28 129.25 0 top
RV192  -  [R_0402]  201.31 131.96 90 bottom
RV193  -  [R_0402]  216.28 132.88 0 bottom
RV194  -  [R_0402]  216.41 117.56 0 bottom
RV195  -  [R_0402]  203.1 114.13 180 bottom
RV196  -  [R_0402]  203.1 116.79 180 top
RV197  -  [R_0402]  216.28 112.16 0 top
RV198  -  [R_0402]  171.22 119.44 90 top
RV199  -  [R_0402]  182.54 94.36 180 top
RV201  -  [R_0402]  154.99 110.19 270 top
RV202  -  [R_0402]  173.4 115.72 180 top
RV203  -  [R_0402]  164.49 98.99 270 top
RV204  -  [R_0402]  172.82 112.34 180 top
RV206  -  [R_0402]  176.25 125.78 180 top
RV207  -  [R_0402]  166.22 112.08 180 top
RV215  -  [R_0402]  179.11 107.45 180 top
RV234  -  [R_0603]  165.26 126.5 180 top
RV235  -  [R_0402]  175.92 101.27 90 bottom
RV236  -  [R_0402]  174.91 102.19 270 bottom
RV237  -  [R_0402]  166.38 98.99 270 top
RV238  -  [R_0402]  168.24 98.07 90 top
RV239  -  [R_0402]  158.4 109.27 90 top
RV240  -  [R_0402]  159.28 110.19 270 top
RV241  -  [R_0402]  160.81 112.54 270 top
RV242  -  [R_0402]  158.52 111.62 90 top
RV243  -  [R_0402]  156.87 109.27 90 top
RV244  -  [R_0402]  154.33 115.14 270 top
RV245  -  [R_0402]  153.38 115.14 270 top
RV246  -  [R_0402]  171.36 110.75 180 top
RV247  -  [R_0402]  167.02 108.4 0 top
RV248  -  [R0402_0OHM]  167.02 107.45 0 top
RV250  -  [R_0402]  188.16 102.24 0 bottom
RV251  -  [R_0402]  177.13 101.27 90 bottom
RV252  -  [R_0402]  178.08 101.27 90 bottom
RX1  -  [R_0402]  19.14 94.49 90 top
RX2  -  [R_0402]  218.98 176.27 90 top
RX3  -  [R_0402]  218.09 177.19 270 top
RX4  -  [R0805_0OHM]  202.05 165.89 180 bottom
RX5  -  [R_0402]  198.71 166.72 0 top
RX6  -  [R_0402]  199.33 163.14 90 bottom
RX7  -  [R0402_0OHM]  216.88 166.84 270 top
RX8  -  [R_0402]  215.99 166.84 270 top
RX9  -  [R_0402]  219.82 167.02 180 bottom
RX12  -  [R_0402]  15.09 110.55 180 bottom
RX13  -  [R_0402]  22.95 108.35 270 bottom
RX14  -  [R_0402]  19.19 115.26 0 bottom
RX15  -  [R_0402]  15.09 112.34 180 bottom
RX16  -  [R_0402]  14.02 108.27 90 top
RX17  -  [R_0402]  14.02 107.4 270 top
RX18  -  [R_0402]  211.36 175.88 0 top
RX19  -  [R0402_0OHM]  214.01 176.74 270 top
RX20  -  [R0402_0OHM]  212.27 176.77 180 top
RX21  -  [R_0402]  218.98 165.73 90 top
RX22  -  [R_0402]  219.87 165.73 90 top
RX23  -  [R_0402]  213.12 176.74 270 top
RX24  -  [R_0402]  20.03 94.49 90 top
RX25  -  [R_0402]  197.63 171.1 180 top
RX26  -  [R_0402]  203.99 165.25 270 bottom
RX27  -  [R0603_0OHM]  217.64 173.56 0 top
RX28  -  [R_0603]  26 94.44 90 bottom
RX29  -  [R_0603]  21.36 93.09 90 top
RX30  -  [R_0402]  196.71 172.35 0 top
RX31  -  [R_0402]  198.45 163.14 90 bottom
RX33  -  [R_0402]  204.68 177.37 0 top
RX34  -  [R_0402]  14.19 113.22 90 bottom
RX35  -  [R_0402]  198.61 172.67 180 bottom
RX36  -  [R_0402]  206.53 165.25 270 bottom
RX37  -  [R_0402]  201.02 172.25 0 bottom
RX38  -  [R_0402]  206.53 171.26 0 bottom
RX39  -  [R_0402]  201.02 171.36 0 bottom
RX40  -  [R_0402]  206.53 170.37 0 bottom
RX41  -  [R_0402]  201.02 170.47 0 bottom
RX42  -  [R_0402]  206.53 169.48 0 bottom
RX43  -  [R_0402]  201.02 169.58 0 bottom
RX44  -  [R_0402]  206.53 168.59 0 bottom
RX45  -  [R_0402]  201.02 168.69 0 bottom
RX46  -  [R_0402]  206.53 167.7 0 bottom
RX47  -  [R_0402]  201.02 167.8 0 bottom
RX48  -  [R_0402]  206.53 166.81 0 bottom
RX49  -  [R_0402]  205.64 165.25 270 bottom
RX50  -  [R_0402]  213.57 162 0 bottom
RX51  -  [R_0402]  207.42 164.34 90 bottom
RX52  -  [R_0402]  198.61 171.78 180 bottom
RX53  -  [R_0402]  208.74 176.99 0 top
RX168  -  [R_0402]  197.64 176.81 270 bottom
RX169  -  [R_0402]  197.64 174.11 90 bottom
RX170  -  [R_0402]  198.53 175.89 90 bottom
RX171  -  [R_0402]  198.53 175.03 270 bottom
SW1  -  [SW_SMT1-05-A_4P]  196.77 27.43 90 top
SW2  -  [SW_SMT1-05-A_4P]  202.92 39.99 180 bottom
T38  -  [TPC12]  116.56 113.31 0 top
T39  -  [TPC12]  89.99 117.2 180 bottom
T40  -  [TPC12]  91.57 117.29 0 top
T41  -  [TPC12]  94.78 118.1 0 top
T42  -  [TPC12]  88.58 117.71 180 bottom
T43  -  [TPC12]  93.47 117.24 0 top
T44  -  [TPC12]  92.41 112.57 0 top
T45  -  [TPC12]  94.26 112.47 0 top
T46  -  [TPC12]  95.63 112.98 0 top
T47  -  [TPC12]  90.01 110.56 180 bottom
T48  -  [TPC12]  93.94 114.11 0 top
T49  -  [TPC12]  93.57 111.04 0 top
T50  -  [TPC12]  94.91 116.78 0 top
T51  -  [TPC12]  94.26 115.45 0 top
T53  -  [TPC12]  122.01 120.66 0 top
T55  -  [TPC12]  122.3 109.29 0 top
T56  -  [TPC12]  124.77 114.54 0 top
T58  -  [TPC12]  122.63 112.48 0 top
T59  -  [TPC12]  125.57 113.45 0 top
T78  -  [TPC12]  183.8 111.33 270 top
T79  -  [TPC12]  174.88 110.16 270 top
T80  -  [TPC12]  171.07 117.05 270 top
T81  -  [TPC12]  171.03 118.36 270 top
T82  -  [TPC12]  162.2 134.21 90 bottom
T83  -  [TPC12]  193.57 100.97 90 bottom
T84  -  [TPC12]  164.58 102.04 90 bottom
T85  -  [TPC12]  163.07 114.76 180 bottom
T86  -  [TPC12]  162.88 113.4 180 bottom
T87  -  [TPC12]  162.97 112.09 180 bottom
T88  -  [TPC12]  161.03 113.73 180 bottom
T89  -  [TPC12]  161.69 114.83 180 bottom
T90  -  [TPC12]  172.49 109.32 0 top
T91  -  [TPC12]  172.9 111.08 0 top
T94  -  [TPC12]  40.69 78.59 180 bottom
T95  -  [TPC12]  40.17 81.11 180 bottom
T96  -  [TPC12]  40 79.82 180 bottom
T97  -  [TPC12]  133.76 112.72 180 bottom
T98  -  [TPC12]  135.33 112.8 180 bottom
T99  -  [TPC12]  133.02 111.34 180 bottom
T102  -  [TPC12]  126.95 111.57 0 top
T103  -  [TPC12]  136.3 98.31 0 top
T104  -  [TPC12]  128.02 110.63 0 top
T105  -  [TPC12]  128.09 109.3 0 top
T106  -  [TPC12]  133.57 106.39 180 bottom
T107  -  [TPC12]  123.72 111.07 0 top
T111  -  [TPC12]  88.85 122.52 0 top
T112  -  [TPC12]  88.61 121.74 180 bottom
T113  -  [TPC12]  94.78 120.97 0 top
T114  -  [TPC12]  90.52 122.31 0 top
T115  -  [TPC12]  93.34 118.74 0 top
T116  -  [TPC12]  94.2 119.77 0 top
T117  -  [TPC12]  127.8 112.55 0 top
T118  -  [TPC12]  123.23 99.85 0 top
T119  -  [TPC12]  124.12 105.74 0 top
T120  -  [TPC12]  122.02 123.55 0 top
T121  -  [TPC12]  123.5 125.52 0 top
T124  -  [TPC12]  128.98 117.52 0 top
T125  -  [TPC12]  133.45 114.45 180 bottom
T126  -  [TPC12]  129.63 109.45 0 top
T127  -  [TPC12]  128.36 107.9 0 top
T128  -  [TPC12]  135.19 104.82 180 bottom
T129  -  [TPC12]  116.4 119.3 0 top
T130  -  [TPC12]  115.59 117.82 0 top
T131  -  [TPC12]  115.88 116.25 0 top
T132  -  [TPC12]  102.65 99.91 180 bottom
T133  -  [TPC12]  124.26 117.08 0 top
T134  -  [TPC12]  103.76 101.2 180 bottom
T135  -  [TPC12]  121.85 125.4 0 top
T136  -  [TPC12]  133.63 108.15 180 bottom
T137  -  [TPC12]  124.35 107.12 0 top
T138  -  [TPC12]  118.08 122.82 0 top
T139  -  [TPC12]  134.75 98.26 0 top
T140  -  [TPC12]  117.44 121.61 0 top
T141  -  [TPC12]  124.97 98.11 0 top
T142  -  [TPC12]  123.5 101.52 0 top
T143  -  [TPC12]  118.65 119.33 0 top
T144  -  [TPC12]  124.46 99.1 180 bottom
T145  -  [TPC12]  123.6 100.65 180 bottom
T146  -  [TPC12]  89.13 97.09 180 bottom
T147  -  [TPC12]  87.58 96.36 180 bottom
T148  -  [TPC12]  88.62 125.25 180 bottom
T149  -  [TPC12]  88.53 123.97 180 bottom
T150  -  [TPC12]  104.55 128.92 180 bottom
T151  -  [TPC12]  98.86 127.41 180 bottom
T152  -  [TPC12]  99.98 128.73 180 bottom
T153  -  [TPC12]  88.61 119.01 180 bottom
T154  -  [TPC12]  92.06 118.67 0 top
T155  -  [TPC12]  115.58 114.73 0 top
T156  -  [TPC12]  117.41 114.89 0 top
T157  -  [TPC12]  88.79 98.96 180 bottom
T158  -  [TPC12]  93.18 128.89 180 bottom
T159  -  [TPC12]  130.03 128.55 180 bottom
T160  -  [TPC12]  120.29 117.61 0 top
T161  -  [TPC12]  133.29 124.05 180 bottom
T162  -  [TPC12]  120.03 116.12 0 top
T163  -  [TPC12]  134.41 124.69 180 bottom
T164  -  [TPC12]  117.64 120.22 0 top
T165  -  [TPC12]  120.14 121.05 0 top
T166  -  [TPC12]  90.33 99.36 180 bottom
T167  -  [TPC12]  133.57 126.66 180 bottom
T168  -  [TPC12]  133.5 128.03 180 bottom
T169  -  [TPC12]  89.4 129.86 180 bottom
T170  -  [TPC12]  88.58 127.44 180 bottom
T171  -  [TPC12]  133.7 104.66 180 bottom
T172  -  [TPC12]  134.09 102.35 180 bottom
T173  -  [TPC12]  90.68 97.6 180 bottom
T174  -  [TPC12]  126.86 113.55 0 top
T175  -  [TPC12]  126.94 118.35 0 top
T176  -  [TPC12]  126.28 119.55 0 top
T177  -  [TPC12]  127.66 117.24 0 top
T178  -  [TPC12]  125.25 118.36 0 top
T179  -  [TPC12]  132.08 120.33 180 bottom
T180  -  [TPC12]  132.43 121.58 180 bottom
T181  -  [TPC12]  134.41 122.05 180 bottom
T182  -  [TPC12]  126.18 109.54 0 top
T183  -  [TPC12]  151.36 81.11 180 bottom
T184  -  [TPC12]  153.18 81.11 180 bottom
T185  -  [TPC12]  153.11 78.7 180 bottom
T186  -  [TPC12]  151.34 78.66 180 bottom
TL1  -  [BOTH_NS0013LF_16P]  30.91 88.15 270 bottom
U2301  -  [TPS22966DPUR_SON14_2X3]  97.81 28.39 180 bottom
U2302  -  [W25Q64FVSSIG_SO8]  150.53 85.5 90 bottom
U2303  -  [74AUP1G07GW_TSSOP5]  43.47 66.04 0 top
U2304  -  [TPS22966DPUR_SON14_2X3]  140.75 22.1 0 top
UA1  -  [ALC3221-CG_MQFN48_6X6]  30.06 18.45 90 top
UC1  -  [HASWELL-MCP-E-ULT_BGA_1168P-T]  130.28 125.56 0 bottom
UC3  -  [MC74VHC1G08DFT2G_SC70-5]  148.25 105.93 180 top
UC4  -  [74CBTLV3126BQ_DHVQFN14_2P5X3]  71.1 106.53 270 bottom
UD1  -  [MC74VHC1G08DFT2G_SC70-5]  49.64 17.39 270 top
UE1  -  [KB9012QF-A2_LQFP128_14X14]  183.19 35.68 0 top
UE2  -  [SN74LVC1G06DCKR_SC70-5]  178.13 52.42 0 top
UE3  -  [G993P1UF_SOP8]  46.26 103.37 0 bottom
UG1  -  [SLG3NB274VTR_TQFN16_2X3]  70.63 40.63 0 top
UI2  -  [AP2301MPG-13_MSOP8]  28.53 52.06 90 top
UI3  -  [AP2301MPG-13_MSOP8]  25.41 61.43 90 top
UI4  -  [AP2301MPG-13_MSOP8]  20.34 30.98 90 top
UI5  -  [AP2301MPG-13_MSOP8]  205.87 42.12 0 top
UL1  -  [RTL8106E-CG_QFN32_4X4]  35.67 82.87 90 bottom
UL2  -  [APL3512ABI-TRG_SOT23-5]  49.51 83.26 270 bottom
UR1  -  [RTS5179-GR_QFN24_4X4]  175.82 21.39 0 top
UV1  -  [2160809000A11SEYMOU_FCBGA_962P]  192.86 133.09 180 bottom
UV13  -  [MC74VHC1G08DFT2G_SC70-5]  158.91 109.09 90 bottom
UV18  -  [K4B4G1646B-HYH9_FBGA_96P]  162.99 144.45 90 top
UV19  -  [K4B4G1646B-HYH9_FBGA_96P]  162.99 150.85 270 bottom
UV20  -  [K4B4G1646B-HYH9_FBGA_96P]  195.18 150.85 270 top
UV21  -  [K4B4G1646B-HYH9_FBGA_96P]  195.18 144.45 90 bottom
UV22  -  [K4B4G1646B-HYH9_FBGA_96P]  206.55 139.3 0 top
UV23  -  [K4B4G1646B-HYH9_FBGA_96P]  212.95 139.3 180 bottom
UV24  -  [K4B4G1646B-HYH9_FBGA_96P]  206.55 107.62 0 bottom
UV25  -  [K4B4G1646B-HYH9_FBGA_96P]  212.95 107.62 180 top
UX1  -  [APL3512ABI-TRG_SOT23-5]  215.68 168.08 0 top
UX2  -  [MC74VHC1G08DFT2G_SC70-5]  210.43 161.22 90 bottom
UX4  -  [RTD2136R-CG_QFN48_6X6]  201.27 172.58 270 top
YC1  -  [Y_Q13FC1350000_2P]  146.86 100.72 0 bottom
YC2  -  [Y_X3G024000DC1H_4P]  115.52 135.76 0 top
YG1  -  [Y_FSX3M-25PM20FDO_4P]  63.7 39.53 0 top
YL2  -  [Y_FSX3M-25PM20FDO_4P]  36.77 78.15 0 bottom
YV1  -  [Y_7V27000011_4P]  172.39 98.21 180 bottom

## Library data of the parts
C35-C38 C50-C58 C61-C64 C67-C69 C71 C73 C75-C77 C79-C81 C83 C85 C87 C88 C2326 C2327 C5212 CA21 CA22 CA24 CA25 CA29-CA33 CA38-CA40 CA51 CA54 CA56 CA58 CA60 CA65 CA69 CC14 CC15 CC23 CC25 CC27-CC35 CC40 CD31 CD63 CD64 CE5 CE6 CE11 CE12 CE15 CE18-CE20 CE23 CE24 CE26-CE36 CG1-CG4 CG7-CG11 CI2-CI4 CI7 CI9-CI11 CI13-CI17 CI19 CI22 CI24-CI26 CI30 CI32 CL15 CL19 CL20 CL22 CL26 CL30 CL31 CL34-CL37 CL39 CL41 CM40 CM44 CM46-CM49 CR1 CR3-CR7 CR9-CR11 CS5 CS6 CS8-CS11 CS13-CS15 CS17 CS105 CS106 CS108 CS109 CV43-CV50 CV75 CV76 CV78 CV79 CV81 CV83 CV84 CV87 CV88 CV92-CV95 CV108 CV109 CV112-CV115 CV118 CV119 CV121 CV122 CV124-CV130 CV132 CV133 CV141-CV150 CV152-CV156 CV171-CV174 CV188-CV190 CV193-CV196 CV198 CV199 CV201-CV212 CV216-CV247 CV252-CV294 CV299-CV308 CV310-CV318 CV325 CV326 CV329 CV331 CV333 CV335 CX1 CX2 CX4 CX6 CX9-CX21 CX23-CX34 CX37-CX44 CX46 CX47 PC1-PC5 PC7 PC8 PC13-PC16 PC102 PC104 PC108 PC110 PC113 PC114 PC201-PC203 PC207 PC208 PC210 PC300 PC303 PC304 PC307 PC401 PC403 PC404 PC501 PC502 PC504 PC506 PC507 PC509-PC514 PC519-PC523 PC601 PC603 PC604 PC702 PC705 PC708 PC711 PC715 PC717 PC719 PC720 PC722 PC723 PC806 PC809 PC813 PC814 PC816-PC821 PC831 PC832 PC840-PC866 PC869 PC871-PC873 PC1100 PC1101 PC1104 PC1106 PC1200 PC1203 PC1209 PC1214 PC1302 PC1304 PC1306 PC1307 = C_0402
C39-C45 C60 C66 C72 C74 C78 C82 C2305 C2306 C2308 C2309 C2311-C2314 C2316 C2318 C2322-C2324 CA1 CA2 CA23 CA53 CA55 CA57 CA59 CA61-CA64 CA67 CA68 CA71 CA74 CC26 CD59 CD62 CE22 CE25 CG6 CI40 CI43 CI44 CL38 CM43 CM45 CR2 CR8 CS16 CV77 CV80 CV82 CV86 CV91 CV101-CV103 CV110 CV111 CV116 CV117 CV120 CV123 CV131 CV134 CV136-CV140 CV151 CV170 CV187 CV197 CV200 CV213-CV215 CV248-CV251 CV295-CV298 CV322-CV324 CX5 CX22 CX35 CX45 PC100 PC103 PC105 PC106 PC109 PC111 PC200 PC204 PC209 PC301 PC302 PC312 PC313 PC503 PC505 PC508 PC701 PC706 PC707 PC709 PC710 PC721 PC803 PC807 PC810 PC811 PC815 PC835 PC867 PC868 PC870 PC1103 PC1105 PC1205 PC1210 PC1212 PC1213 = C_0603
C59 C65 C70 C84 C86 CL33 = C_1206
C2307 C2310 CE16 CG5 CI6 CI12 CI18 CI21 CI23 CI27 CI31 CS7 CS12 CV97 CX3 CX7 CX8 CX36 CX48 PC112 PC115 PC205 PC206 PC211 PC212 PC305 PC306 PC308-PC311 PC400 PC402 PC405 PC517 PC518 PC600 PC602 PC605 PC703 PC704 PC712-PC714 PC716 PC718 PC804 PC805 PC808 PC901-PC923 PC1102 PC1201 PC1202 PC1204 PC1206 PC1207 PC1211 PC1300 PC1301 PC1303 PC1305 PC1308 = C_0805
CC1-CC11 CC13 CC16-CC22 CC24 = C_0402: room: CPU
CD1-CD11 CD21-CD27 CD30 CD32-CD42 CD52-CD57 CD60 CD61 = C_0402: room: MEMORY
CD12-CD14 CD16-CD20 CD28 CD29 CD43-CD50 CD58 = C_0603: room: MEMORY
CD15 CD51 = C_D3: room: MEMORY
CE1 CE2 = C_0402: room: EDP
CE7-CE9 = C_0402: room: DOCK
CI1 CI8 CI20 PC101 PC107 = C_MP6VLPS220MC4R2
CMOS1 ME1 = SHORTPADS: User Part Number: PART#; room: CPU
CV135 = C_B2
CV327 = C_D2
DA8 = BAT54C-7-F_SOT23-3
DA10 DA12 = AZ5125-02SPR7G_SOT23-3
DC1 = BAT54CW_SOT323-3
DE1 PD101 = L03ESDL5V0CG3-2_SOT-523-3
DH1 DX1 PD701 = RB751V-40_SOD323-2
DI1 DI4 = IP4292CZ10-TBR_XSON10_2P5X1
DI2 DI5 DI7 = L30ESDL5V0C3-2_SOT23-3
FD1-FD4 = FIDUCIAL_C40M80: room: LED
FX1 = F_1206L150PR
H2 H4 H5 H8 H9 H12 H16 H17 = H_2P8: room: LED
H6 H10 = H_3P3: room: LED
H7 H18 = H_3P3
H11 = H_2P8
H31-H34 = H_3P7
H35 = H_3P7X3P2N
J9 JP3 JP8 JP9 JP12 PJP203 = JUMP_43X39
J510 J511 J513 JP7 JP13 PJP400 PJP401 PJP600 PJP601 PJP1300 PJP1301 = JUMP_43X79
JDB = JESS_UCNR2210M008-0_8P
JDIMM1 JDIMM2 = LCN_DAN06-K4406-0102_204P: room: MEMORY
JFAN = ACES_85204-0300N_3P
JHDD = SANTA_193202-1_22P
JHDMI = LOTES_ABA-HDM-022-K01_19P
JHP = SINGA_2SJ3080-000111F_6P-T
JKB = HB_A823020-SBHR21_30P
JLAN = SANTA_130456-311_8P
JLVDS = STARC_107K40-000001-G2_40P
JMINI = CONCR_525B01BE17A_52P
JODD = SANTA_202801-1_13P
JPWR = HB_A090420-SAHR21_4P
JREAD = T-SOL_143-2300302602_22P_RV
JRTC = LOTES_AAA-BAT-054-K01_2P
JSPK = E-T_3703-Q04N-11R_4P
JTOUCH = ACES_88460-00601-P01_6P
JTP = PS_HPF10052-06M000R_6P
JUSB1 JUSB2 = ACON_TARA4-9K1311_9P: room: ETY-ROOM
JUSB3 = ACON_UARBG-4K1926_4P
JXDP1 = SAMTE_BSH-030-01-L-D-A_60P: room: CPU
L1-L5 = MURAT_LQM2MPN2R2NG0L_2P
LA1 = MURAT_BLM15BB221SN1D_2P
LA3-LA6 PR200 PR206 PR405 PR516 PR519 PR536 PR605 PR709 PR822 PR1101 R245 R2314 R2315 RL19 RL20 RV234 RX28 RX29 = R_0603
LA7-LA10 = KC_FBMA-L10-160808-800LMT_2P
LE1 = KC_FBMA-L11-160808-800LMT_2P: room: EDP
LE2 LV21 LV23 = KC_FBMA-L11-160808-800LMT_2P
LED1 = LED_12-21C-T3D-CM2P1B18X-2C_3P: room: LED
LED2 LED4 = LED_12-21C-T3D-CM2P1B18X-2C_3P
LED3 = LED_HT-210UD5-BP5_3P
LI1 LI3 LI4 LI6 = MURAT_DLW21SN670HQ2L_4P
LI2 LI5 LI7 LI10 LR2 LX2-LX6 = KC_WCM-2012HS-900T_4P
LV12-LV16 LV19 LV20 LV22 LV25 LV26 PH1 PH501 PH502 PH800 PR1-PR4 PR6-PR10 PR15-PR18 PR20 PR23 PR24 PR26-PR33 PR102-PR109 PR111 PR114 PR204 PR205 PR207 PR208 PR301 PR304-PR308 PR402-PR404 PR501-PR510 PR512-PR515 PR517 PR518 PR524 PR526 PR528-PR533 PR540 PR602-PR604 PR701 PR703 PR706 PR707 PR711-PR713 PR721 PR723 PR724 PR808 PR813 PR815-PR821 PR824-PR829 PR833-PR840 PR842 PR1102 PR1105 PR1107 PR1108 PR1110 PR1201-PR1204 PR1208 PR1209 PR1211-PR1214 PR1300-PR1302 PR1304 R1 R2 R10 R16 R159 R250 R252-R256 R286 R2313 R2318 R2329-R2338 R2341 R2346-R2352 R2354-R2359 RA1-RA3 RA5-RA9 RA19 RA51 RA53 RA55 RA56 RA79-RA84 RA130 RA153 RA165 RA166 RA1109 RC10 RC11 RC13 RC21 RC32 RC37 RC56 RC62 RC63 RC65 RC66 RC68 RC75 RC77 RC78 RC89 RC98-RC100 RC105 RC112 RC113 RC123 RC124 RC127-RC132 RC135 RC139 RC362 RD12-RD18 RD45-RD52 RE1-RE3 RE7-RE12 RE18 RE36 RE43 RE47 RE49 RE50 RE60 RE71 RE326 RG1-RG8 RL27 RL31 RL33-RL35 RL37 RL38 RM11 RM13 RM110 RR1-RR3 RS6-RS8 RV64 RV66 RV73-RV76 RV81-RV85 RV89-RV91 RV93 RV95 RV97 RV105 RV107-RV109 RV122 RV123 RV125 RV127 RV133 RV136-RV199 RV201-RV204 RV206 RV207 RV215 RV235-RV247 RV250-RV252 RX1-RX3 RX5 RX6 RX8 RX9 RX12-RX18 RX21-RX26 RX30 RX31 RX33-RX53 RX168-RX171 = R_0402
LV17 LV18 = CHENG_MBK1608121YZF_2P
LX1 LX7 LX8 = KC_FBMA-L11-201209-221LMA30_2P
LX9 = CYNTE_PG031B-4R7MS_2P
PBATT = SUYIN_200028MR009G502ZL_9P
PC213 PC1108 = C_MP6VU330MC6
PC515 PC516 PC724 = C_EEEFZ1E101P
PC836-PC839 = C_D1
PD1 = IP4223CZ6_SO6
PD2 PD3 = TVNST52302AB0_SOT523-3
PJP100-PJP103 PJP200 PJP201 PJP300 PJP1100 PJP1101 PJP1200 = JUMP_43X118
PJPDC = ACES_50299-00501-003_5P
PL1 PL2 PL4 = CHT_C8BBPH853025_2P
PL3 = CHENG_SMB3025500YA_2P
PL100 PL101 PL1300 = VISHAY_IHLP-2525CZ-01_2P
PL102 PL702 = CYNTE_PCMB053T-1R0MS_2P
PL200 = TAI-T_VMPI0703AR-1R0M-Z01_2P
PL201 PL302 PL501 PL800 PL1201 = L_1812-1806
PL301 PL1200 = CYNTE_PCMB063T-1R0MS_2P
PL400 PL600 = TAIYO_NRS4018T1R0NDGJ_2P
PL502 = TOKO_FDUE1040J-H-R36M-P3_4P
PL701 = TOKO_FDVE1040-H-2R2M-P3_2P
PL802 = MAG_MMD-12CE-R36M-M1L_2P
PL1100 = TAI-T_HCB2012KF-121T50_2P
PL1101 = PANAS_ETQP3W2R2WFN_2P
PQ1-PQ3 = 2N7002DW-T-R7_SOT363-6
PQ4 PQ706 PQ708 = SSM3K7002FU_SC70-3
PQ5 = RHU002N06_SOT323-3
PQ6 = FDV301N_NL_SOT23-3
PQ101-PQ104 PQ200 PQ201 PQ1100 PQ1101 = SIS412DN-T1-GE3_POWERPAK8-5
PQ701 = CSD87312Q3E_SON8-4
PQ702 = AO4407AL_SO8
PQ703 PQ704 = MDU1516URH_POWERDFN56-8-5
PQ705 = MDU1511RH_POWERDFN56-8-5
PQ800 PQ803 = SIR472DP-T1-GE3_POWERPAK8-5
PQ801 PQ802 = SIR818DP-T1_POWERPAK-SO8-5
PQ1201 = 2N7002W-T-R7_SOT323-3
PR5 PR112 PR113 PR203 PR302 PR534 PR705 PR720 PR722 PR805 PR1104 PR1207 PR1303 = R_1206
PR100 PR101 PR201 PR202 PR300 PR401 PR522 PR535 PR601 PR704 PR708 PR710 PR714 PR715 PR717 PR803 PR804 PR806 PR807 PR809-PR812 PR830 PR845 PR846 PR1103 PR1206 PR1210 R248 R251 R257 R265 R416 RA4 RC57 RC59 RC141 RE37 RE44 RV118-RV121 RV124 RV126 RV248 RX7 RX19 RX20 = R0402_0OHM
PR303 PR802 PR814 PR823 PR1200 R264 RA29-RA32 RC126 RV54 RV59 RX27 = R0603_0OHM
PR702 PR716 = R_1206_4P-D
PU100 = TPS51225CRUKR_QFN20_3X3
PU200 = RT8207MZQW_WQFN20_3X3
PU300 PU1200 = SY8206DQNC_QFN10_3X3
PU400 PU600 = SY8003DFC_DFN8_2X2
PU501 = TPS51622RSM_QFN32_4X4
PU502 = CSD97374CQ4M_SON8_3P5X4P5-S
PU701 = BQ24738RGRR_QFN20_3P5X3P5
PU800 = ISL62881HRZ-T_QFN28_4X4
PU1100 = TPS51212DSCR_SON10_3X3
PU1300 = SY8036DBC_DFN10_3X3
Q8 Q2307 Q2308 QC3 QD18-QD20 QM30 QV24 QV25 QV28 QX3 = 2N7002K_SOT23-3
QA5 QA6 QH1 QV14 QV15 QX4 QX6 = DMN66D0LDW-7_SOT363-6
QC1 = DMN66D0LDW-7_SOT363-6: room: CPU
QD2 = BSS138-G_SOT23-3
QS2 = SI3456BDV-T1-E3_TSOP6
QS3 QX1 = 2N7002KW_SOT323-3
QV22 = AP2301GN-HF_SOT23-3
QX2 = SI3457CDV-T1-GE3_TSOP6
QX5 = MMBT3904_NL_SOT23-3
R267 RM25 RM26 RX4 = R0805_0OHM
RC1-RC9 RC12 RC14-RC20 RC22-RC25 RC27-RC29 RC31 RC34-RC36 RC48-RC52 RC58 RC60 RC64 RC67 RC69-RC74 RC76 RC84 RC87 RC88 RC90 RC91 RC97 RC101-RC104 RC106-RC108 RC110 RC111 RC116 RC118-RC122 RC125 RC133 RC134 RC138 RC140 RC163 = R_0402: room: CPU
RC26 RC33 RC41-RC46 RC81 = R0402_0OHM: room: CPU
RD1 RD4 RD5 RD8 RD10 = R0402_0OHM: room: MEMORY
RD3 RD6 RD7 = R_0402: room: MEMORY
RE5 = R_0402: room: DOCK
RP36 RP37 RP39-RP60 = RP_0804_8P4R
RV103 = R_0805
SW1 SW2 = SW_SMT1-05-A_4P
T38-T51 T53 T55 T56 T58 T59 T78-T91 T95 T96 T102 T103 T105 T111-T114 T116 T117 T119 T120 T124-T127 T129-T186 = TPC12
T94 = TPC12: room: LOM
T97-T99 T104 T106 T107 T115 T118 T121 = TPC12: room: SIO
T128 = TPC12: room: KBC
TL1 = BOTH_NS0013LF_16P
U2301 U2304 = TPS22966DPUR_SON14_2X3
U2302 = W25Q64FVSSIG_SO8
U2303 = 74AUP1G07GW_TSSOP5
UA1 = ALC3221-CG_MQFN48_6X6
UC1 = HASWELL-MCP-E-ULT_BGA_1168P-T: room: CPU
UC3 = MC74VHC1G08DFT2G_SC70-5: room: CPU
UC4 = 74CBTLV3126BQ_DHVQFN14_2P5X3: room: CPU
UD1 UV13 UX2 = MC74VHC1G08DFT2G_SC70-5
UE1 = KB9012QF-A2_LQFP128_14X14
UE2 = SN74LVC1G06DCKR_SC70-5
UE3 = G993P1UF_SOP8
UG1 = SLG3NB274VTR_TQFN16_2X3
UI2-UI5 = AP2301MPG-13_MSOP8
UL1 = RTL8106E-CG_QFN32_4X4
UL2 UX1 = APL3512ABI-TRG_SOT23-5
UR1 = RTS5179-GR_QFN24_4X4
UV1 = 2160809000A11SEYMOU_FCBGA_962P
UV18-UV25 = K4B4G1646B-HYH9_FBGA_96P
UX4 = RTD2136R-CG_QFN48_6X6
YC1 = Y_Q13FC1350000_2P: room: CPU
YC2 = Y_X3G024000DC1H_4P: room: CPU
